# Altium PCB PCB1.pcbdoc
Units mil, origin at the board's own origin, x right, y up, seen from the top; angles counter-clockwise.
Board outline 2086.61 x 986.1 mil, 4 copper layers (Top Layer, AGND, Power, Bottom Layer), stack 62.447 mil thick; 45 components, 23 nets, 118 pads, 113 vias.
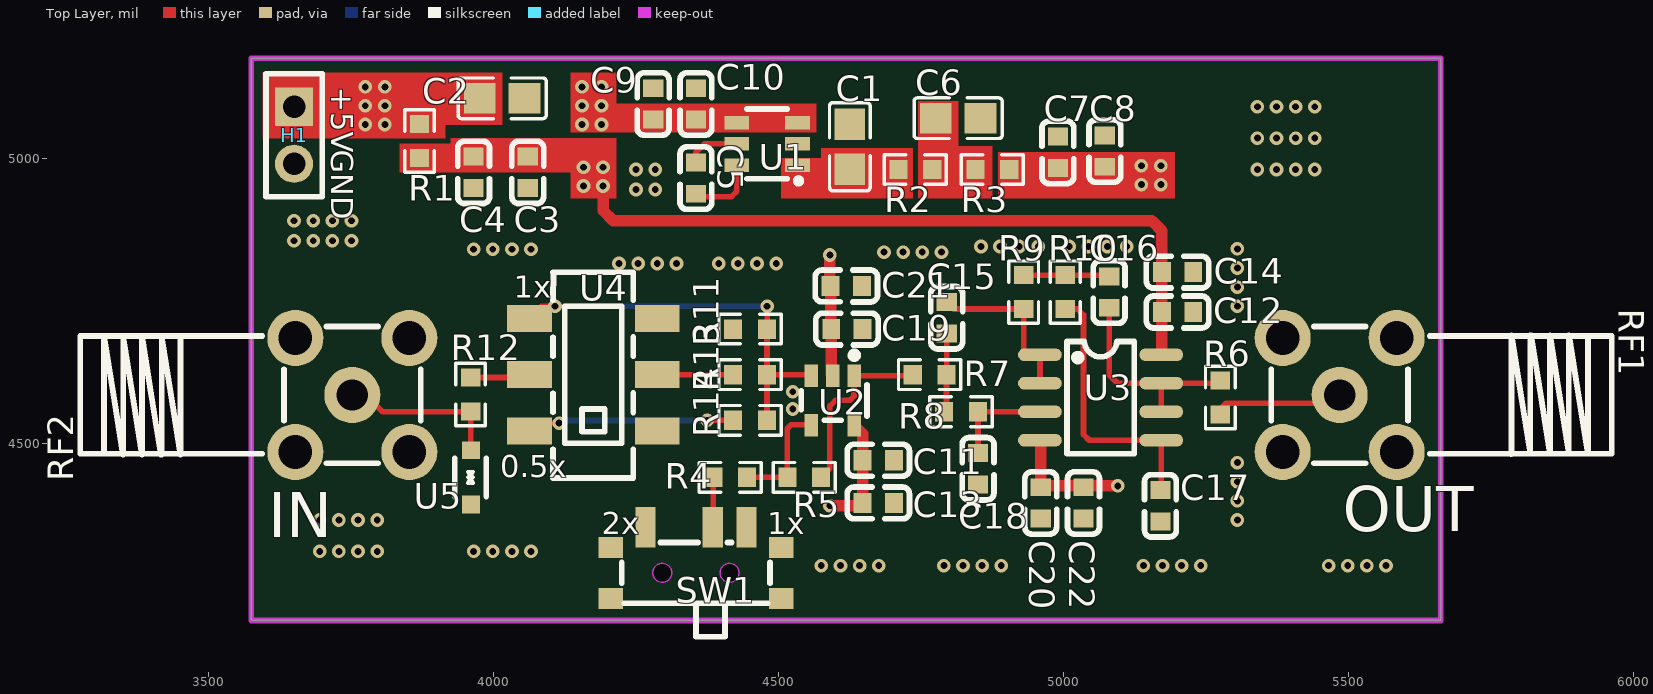
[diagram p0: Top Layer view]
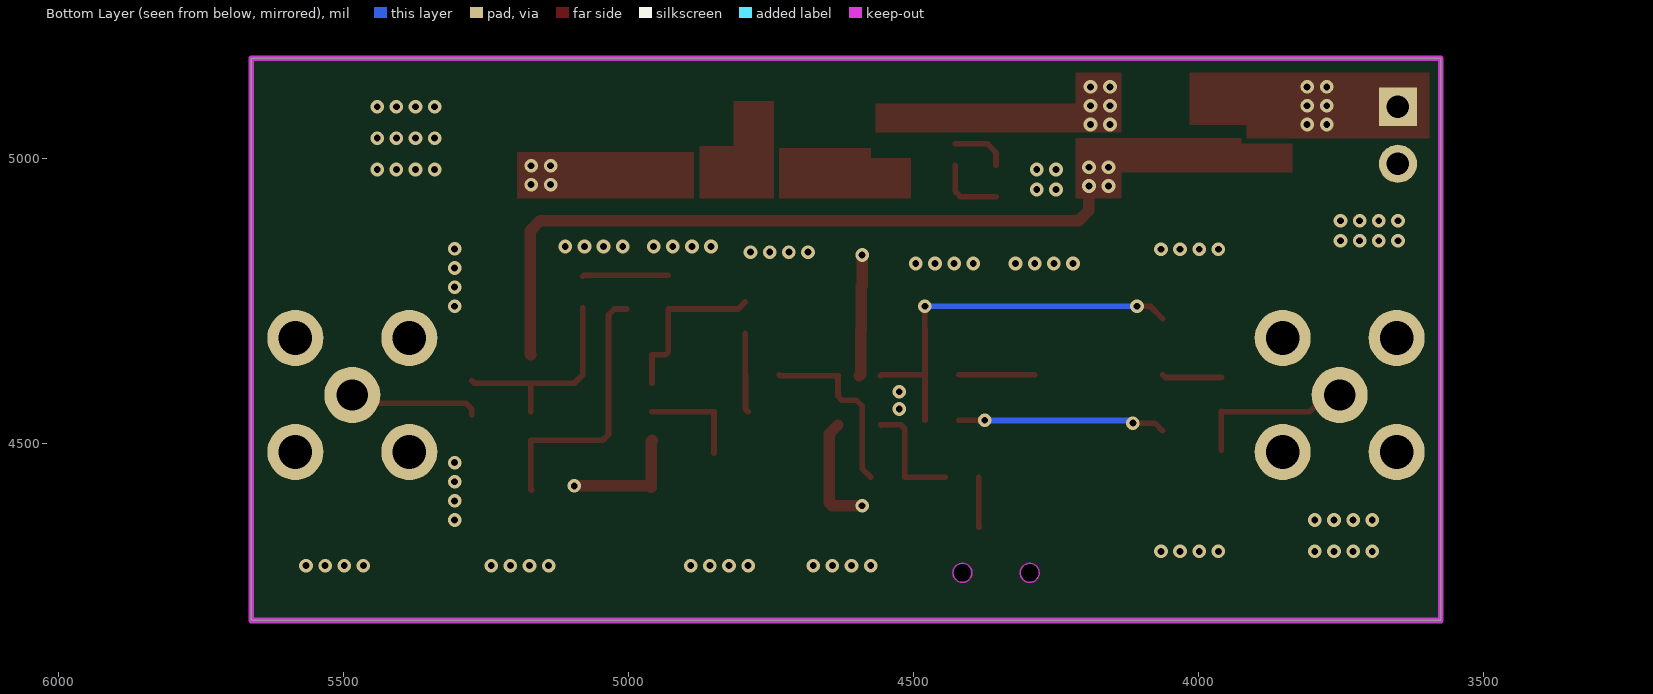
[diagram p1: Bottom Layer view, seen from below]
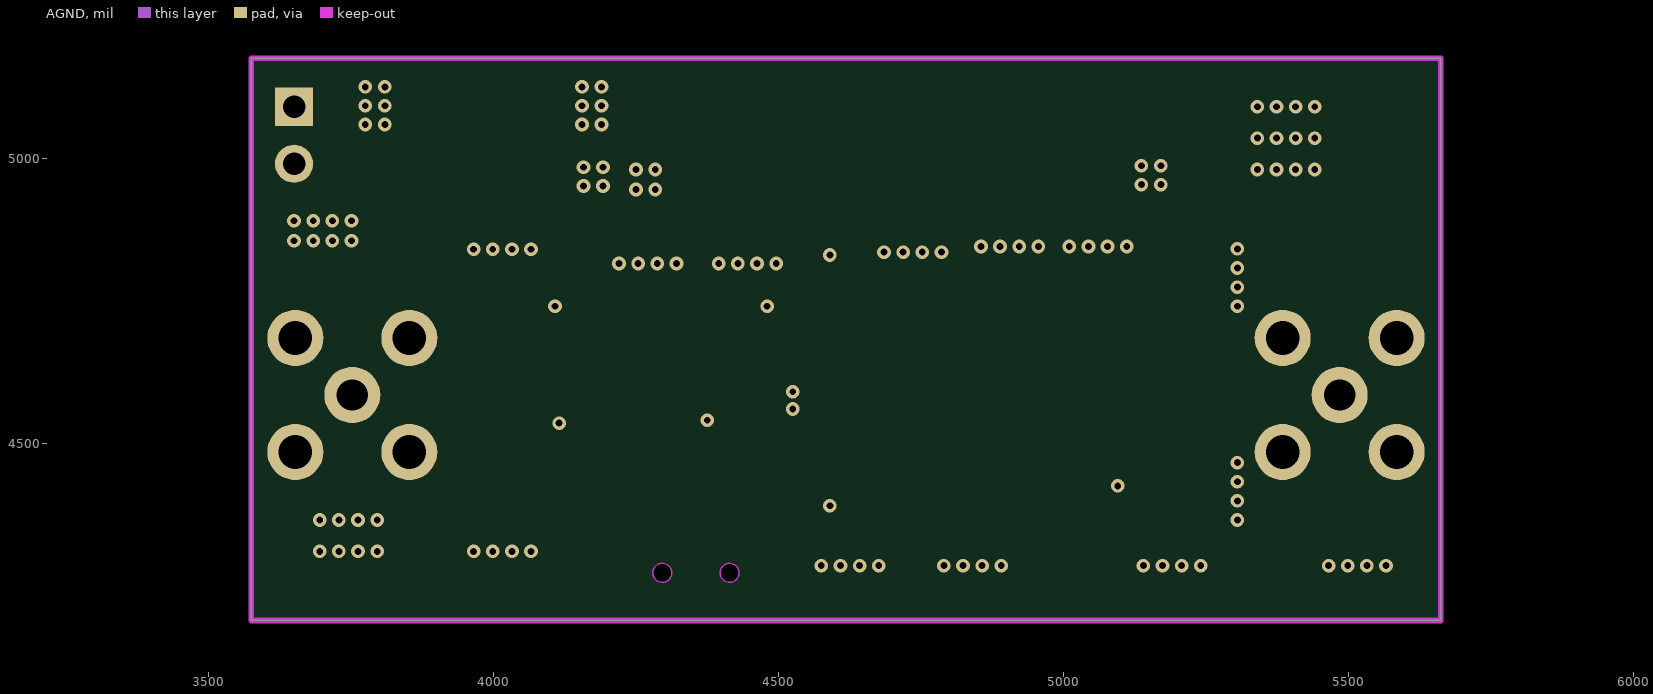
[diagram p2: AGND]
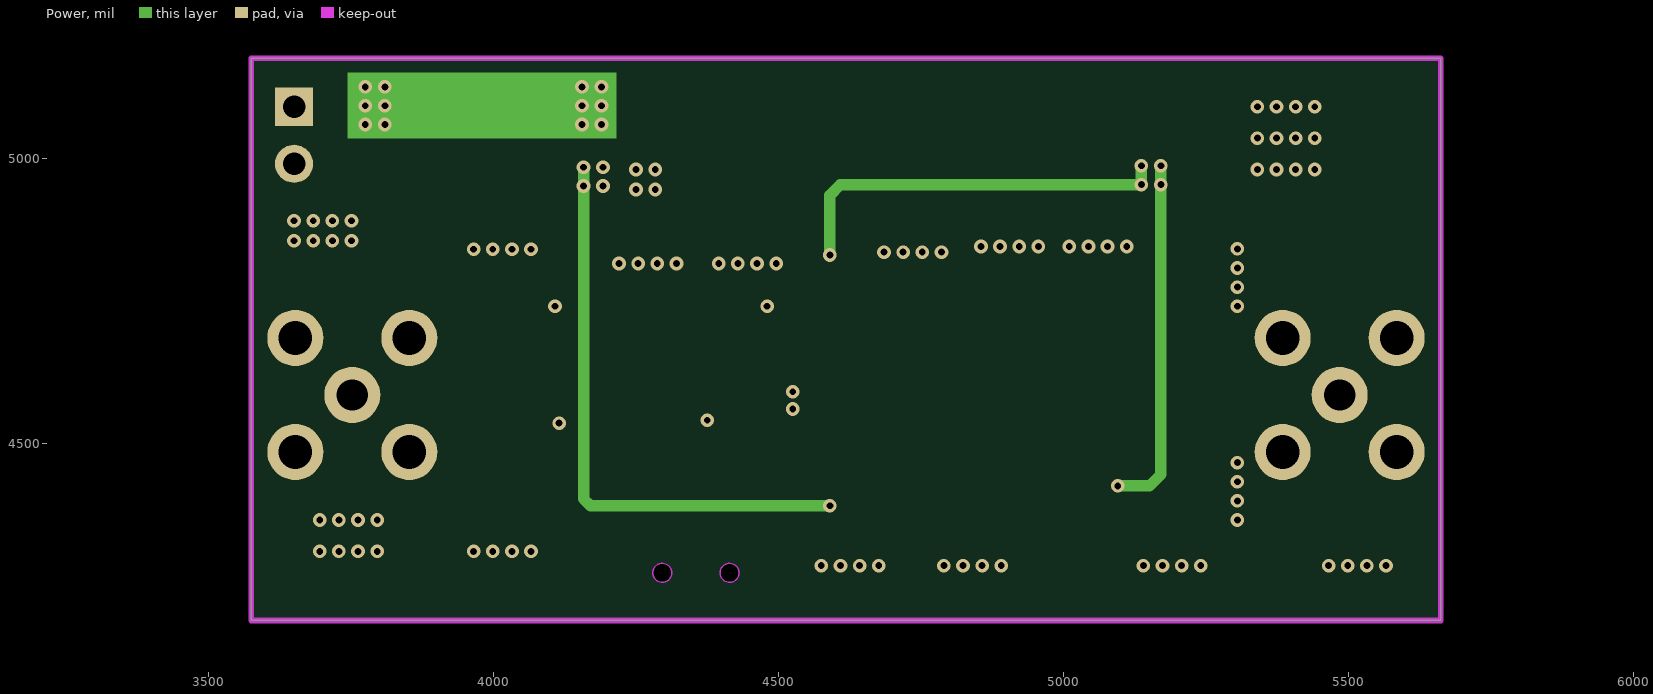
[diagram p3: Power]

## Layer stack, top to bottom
Top Layer: signal copper 1.378
Dielectric1: surface 8.283, 7628 RC49% 8.6mil, Dk 4.4
AGND: signal copper 0.598
Dielectric2: surface 41.929, 1.1mm H/HOZ Copper, Dk 4.43
Power: signal copper 0.598
Dielectric3: surface 8.283, 7628 RC49% 8.6mil, Dk 4.4
Bottom Layer: signal copper 1.378

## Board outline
3575,5175 3575,4188.9 5661.61,4188.9 5661.61,5175

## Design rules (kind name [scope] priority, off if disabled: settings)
BoardOutlineClearance copperThickness2oz_1 [All] p2 off: genericclearance=7.99 ignorepadtopadclearanceinfootprint=FALSE except(0: Arc-SplitContinuation Track-SplitContinuation SMDPad-SplitContinuation THPad-SplitContinuation Via-SplitContinuation Fill-SplitContinuation Region-SplitContinuation Poly-SplitContinuation Text-SplitContinuation Hole-SplitContinuation; 5.98: Arc-CutoutEdge SMDPad-CutoutEdge THPad-CutoutEdge Via-CutoutEdge Fill-CutoutEdge Region-CutoutEdge Text-CutoutEdge; 6.93: Hole-OutlineEdge Hole-CutoutEdge; 10: Poly-OutlineEdge Poly-CutoutEdge; 11.81: Arc-OutlineEdge Track-OutlineEdge SMDPad-OutlineEdge THPad-OutlineEdge Via-OutlineEdge Fill-OutlineEdge Region-OutlineEdge Text-OutlineEdge Track-CutoutEdge)
BoardOutlineClearance copperThickness1oz_1 [All] p4: genericclearance=4.02 ignorepadtopadclearanceinfootprint=FALSE except(0: Arc-SplitContinuation Track-SplitContinuation SMDPad-SplitContinuation THPad-SplitContinuation Via-SplitContinuation Fill-SplitContinuation Region-SplitContinuation Poly-SplitContinuation Text-SplitContinuation Hole-SplitContinuation; 6: SMDPad-CutoutEdge THPad-CutoutEdge Via-CutoutEdge Fill-CutoutEdge Region-CutoutEdge Text-CutoutEdge; 6.93: Hole-OutlineEdge Hole-CutoutEdge; 10: Poly-OutlineEdge Poly-CutoutEdge; 11.8: Arc-OutlineEdge Track-OutlineEdge SMDPad-OutlineEdge THPad-OutlineEdge Via-OutlineEdge Fill-OutlineEdge Region-OutlineEdge Text-OutlineEdge; 11.81: Arc-CutoutEdge Track-CutoutEdge)
Clearance copperThickness2oz [All] p1 off: gap=7.99 ignorepadtopadclearanceinfootprint=FALSE except(5.98: SMDPad-Track SMDPad-SMDPad THPad-Track SMDPad-THPad THPad-THPad Track-Via SMDPad-Via THPad-Via Via-Via Fill-Track Region-Track Fill-SMDPad Region-SMDPad Fill-THPad Region-THPad Fill-Via Region-Via Fill-Fill Fill-Region Region-Region Arc-Track Arc-SMDPad Arc-THPad Arc-Via Fill-Arc Region-Arc Arc-Arc Text-Track SMDPad-Text Text-THPad Text-Via Fill-Text Region-Text Arc-Text Text-Text; 6.93: Hole-Track Hole-SMDPad Hole-THPad Hole-Via Fill-Hole Region-Hole Hole-Arc Hole-Text; 10: Poly-Track Poly-SMDPad Poly-THPad Poly-Via Poly-Fill Poly-Region Poly-Poly Poly-Arc Poly-Text Poly-Hole)
Clearance copperThickness1oz [All] p3: gap=4.02 ignorepadtopadclearanceinfootprint=FALSE except(5.98: SMDPad-Track SMDPad-SMDPad THPad-Track SMDPad-THPad THPad-THPad Track-Via SMDPad-Via THPad-Via Via-Via Fill-Track Region-Track Fill-SMDPad Region-SMDPad Fill-THPad Region-THPad Fill-Via Region-Via Fill-Fill Fill-Region Region-Region; 6: Arc-Track Arc-SMDPad Arc-THPad Arc-Via Fill-Arc Region-Arc Arc-Arc Text-Track SMDPad-Text Text-THPad Text-Via Fill-Text Region-Text Arc-Text Text-Text; 6.93: Hole-Track Hole-SMDPad Hole-THPad Hole-Via Fill-Hole Region-Hole Hole-Arc Hole-Text; 10: Poly-Track Poly-SMDPad Poly-THPad Poly-Via Poly-Fill Poly-Region Poly-Poly Poly-Arc Poly-Text Poly-Hole)
Creepage creepage [All] p1: checkdistance=0 ignoreinternallayers=TRUE applytopolygonpour=TRUE
DiffPairsRouting differentialPair [All] p1: maxlimit=6 minlimit=6 mostfreqgap=6 toplayer_minwidth=5 toplayer_prefwidth=10 toplayer_maxwidth=100 toplayer_mingap=6 toplayer_prefgap=6 toplayer_maxgap=6 midlayer1_minwidth=5 midlayer1_prefwidth=10 midlayer1_maxwidth=100 midlayer1_mingap=6 midlayer1_prefgap=6 midlayer1_maxgap=6 midlayer2_minwidth=5 midlayer2_prefwidth=10 midlayer2_maxwidth=100 midlayer2_mingap=6 midlayer2_prefgap=6 midlayer2_maxgap=6 bottomlayer_minwidth=5 bottomlayer_prefwidth=10 bottomlayer_maxwidth=100 bottomlayer_mingap=6 bottomlayer_prefgap=6 bottomlayer_maxgap=6 maxuncoupledlength=10
HoleToHoleClearance otherClearance [All] p1: gap=11.81 allowstackedmicrovias=TRUE
Length netLength [All] p1: minlimit=0 maxlimit=0
MatchedLengths netLengthTolerance [All] p1: tolerance=1000
PasteMaskExpansion pasteMaskExpansion [All] p1: expansion=0
PlaneConnect innerPlane [All] p1: planeconnectstyle=Relief reliefexpansion=20 reliefentries=4 reliefconductorwidth=10 reliefairgap=10
PolygonConnect "copperRegion_Top Layer" [(InNet('+5V') OR InNet('AGND')) And OnLayer('Top Layer')] p1: connectstyle=Direct reliefconductorwidth=10 reliefentries=4 polygonreliefangle="90 Angle" airgapwidth=10 via.connectstyle=Relief via.reliefconductorwidth=10 via.reliefentries=4 via.polygonreliefangle="90 Angle" via.airgapwidth=10
PolygonConnect "copperRegion_Bottom Layer" [(InNet('+5V') OR InNet('AGND')) And OnLayer('Bottom Layer')] p2: connectstyle=Direct reliefconductorwidth=10 reliefentries=4 polygonreliefangle="90 Angle" airgapwidth=10 via.connectstyle=Relief via.reliefconductorwidth=10 via.reliefentries=4 via.polygonreliefangle="90 Angle" via.airgapwidth=10
PolygonConnect copperRegion_AGND [(InNet('+5V') OR InNet('AGND')) And OnLayer('AGND')] p3: connectstyle=Direct reliefconductorwidth=10 reliefentries=4 polygonreliefangle="90 Angle" airgapwidth=10 smdpad.connectstyle=Relief smdpad.reliefconductorwidth=10 smdpad.reliefentries=4 smdpad.polygonreliefangle="90 Angle" smdpad.airgapwidth=10 via.connectstyle=Relief via.reliefconductorwidth=10 via.reliefentries=4 via.polygonreliefangle="90 Angle" via.airgapwidth=10
PolygonConnect copperRegion_Power [(InNet('+5V') OR InNet('AGND')) And OnLayer('Power')] p4: connectstyle=Direct reliefconductorwidth=10 reliefentries=4 polygonreliefangle="90 Angle" airgapwidth=10 smdpad.connectstyle=Relief smdpad.reliefconductorwidth=10 smdpad.reliefentries=4 smdpad.polygonreliefangle="90 Angle" smdpad.airgapwidth=10 via.connectstyle=Relief via.reliefconductorwidth=10 via.reliefentries=4 via.polygonreliefangle="90 Angle" via.airgapwidth=10
PolygonConnect copperRegion [(InNet('+5V') OR InNet('AGND'))] p5: connectstyle=Direct reliefconductorwidth=10 reliefentries=4 polygonreliefangle="90 Angle" airgapwidth=10 via.connectstyle=Relief via.reliefconductorwidth=10 via.reliefentries=4 via.polygonreliefangle="90 Angle" via.airgapwidth=10
RoutingVias viaSize [All] p1: holewidth=12.01 width=24.02 viastyle="Through Hole" minholewidth=11.81 minwidth=19.68 maxholewidth=248.03 maxwidth=393.7
SolderMaskExpansion solderMaskExpansion [IsVia] p1: expansion=-1000 istentingtop=TRUE
SolderMaskExpansion solderMaskExpansion [All] p2: expansion=2 istentingtop=FALSE
Width copperThickness2oz_2 [All] p1 off: maxlimit=100 minlimit=8 preferedwidth=10
Width copperThickness1oz_2 [All] p2: maxlimit=100 minlimit=5 preferedwidth=10

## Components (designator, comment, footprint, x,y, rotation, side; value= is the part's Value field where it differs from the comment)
C1 "2.2uF" C0805 4625,5020 r90 top
C2 "10uF" C0805 4015,5105 r180 top
C3 "100nF" C0603 4060,4975 r90 top
C4 "1uF" C0603 3965,4975 r90 top
C5 "1uF" C0603 4355,4965 r270 top
C6 "10uF" C0805 4815,5070 r180 top
C7 "100nF" C0603 4990,5010 r270 top
C8 "1uF" C0603 5072.44,5012.44 r270 top
C9 "1uF" C0603 4280,5095 r270 top
C10 "100nF" C0603 4355,5095 r270 top
C11 "100nF" C0603 4675,4470 r180 top
C12 "100nF" C0603 5200,4730 r180 top
C13 "1uF" C0603 4675,4395 r180 top
C14 "1uF" C0603 5200,4800 r180 top
C15 "150pF" C0603 4795,4720 r270 top
C16 "27pF" C0603 5080,4765 r270 top
C17 "22pF" C0603 5170,4390 r90 top
C18 "22pF" C0603 4850,4455 r90 top
C19 "100nF" C0603 4620,4700 r0 top
C20 "100nF" C0603 4960,4395 r270 top
C21 "1uF" C0603 4618.94,4775.69 r0 top
C22 "1uF" C0603 5035,4395 r270 top
H1 "" HDR-TH_2P-P2.54-V-F 3650,5040 r270 top
R1 "10Ω" R0603 3870,5030 r270 top
R2 "1Ω" R0603 4740,4980 r0 top
R3 "10Ω" R0603 4875,4980 r0 top
R4 "499Ω" R0603 4415,4440 r0 top
R5 "499Ω" R0603 4545,4440 r0 top
R6 "22Ω" R0603 5275,4580 r270 top
R7 "180Ω" R0603 4765,4620 r0 top
R8 "180Ω" R0603 4820,4555 r0 top
R9 "430Ω" R0603 4930,4765 r90 top
R10 "430Ω" R0603 5003.03,4765 r270 top
R11 "10kΩ" R0603 4450,4700 r0 top
R12 "100Ω" R0603 3959.66,4585.34 r90 top
R13 "1kΩ" R0603 4450,4620 r0 top
R14 "820Ω" R0603 4450,4540 r0 top
RF1 "6GHz" SMA-TH_SMA-KWE902 5484.45,4584.45 r270 top
RF2 "6GHz" SMA-TH_SMA-KWE902 3752.17,4584.45 r90 top
SW1 "MK-12C02-G025" SW-SMD_MK-12C02-G025 4355,4290 r0 top
U1 "LM2776DBVR" SOT-23-6_L2.9-W1.6-P0.95-LS2.8-BR 4480,5025 r0 top
U2 "OPA830IDBVR" SOT-23-5_L2.9-W1.6-P0.95-LS2.8-BR 4595,4575 r90 top
U3 "OPA2830IDR" SOIC-8_L5.0-W4.0-P1.27-LS6.0-BL 5065,4580 r270 top
U4 "HX MST22D18G2" SW-SMD_MST22D18G2 4175,4620 r90 top
U5 "WPE12VD3ULA" SOD-323_L1.7-W1.3-LS2.5-BI 3960,4440 r90 top

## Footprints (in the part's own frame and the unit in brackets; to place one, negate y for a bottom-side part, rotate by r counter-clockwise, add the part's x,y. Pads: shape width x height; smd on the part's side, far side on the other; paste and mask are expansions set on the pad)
C0603 [mm]
  rect 0.8x0.9 smd: 1(-0.7,0) 2(0.7,0)
  silkscreen extent -1.39,-0.71 1.39,0.71
C0805 [mm]
  rect 1.41x1.35 smd paste-100 mask+0.051: 1(-1,0) 2(1,0)
  silkscreen extent -1.96,-0.9 1.96,0.9
HDR-TH_2P-P2.54-V-F [mm]
  rect 1.7x1.7 hole 1: 1(-1.27,0)
  round 1.7 hole 1: 2(1.27,0)
  silkscreen extent -2.74,-1.25 2.74,1.25
R0603 [mil]
  rect 31.75x34.02 smd paste-3937.01 mask+2: 1(-29.66,0) 2(29.66,0)
  silkscreen extent -55,-26 55,26
SMA-TH_SMA-KWE902 [mm]
  round 2.5 hole 1.5: 1(-2.54,2.54) 2(2.54,2.54) 3(2.54,-2.54) 4(-2.54,-2.54)
  round 2.5 hole 1.4: 5(0,0)
  silkscreen extent -3.05,-3.05 3.05,12.12
SOD-323_L1.7-W1.3-LS2.5-BI [mm]
  rect 0.8x0.8 smd: 1(-1.205,0) 2(1.205,0)
  silkscreen extent -0.86,-0.68 0.84,0.72
SOIC-8_L5.0-W4.0-P1.27-LS6.0-BL [mil]
  oval 22.38x76.78 smd: 1(-75,-106.5) 2(-25,-106.5) 3(25,-106.5) 4(75,-106.5) 5(75,106.5) 6(25,106.5) 7(-25,106.5) 8(-75,106.5)
  silkscreen extent -98,-59 98,59
SOT-23-5_L2.9-W1.6-P0.95-LS2.8-BR [mm]
  rect 1x0.6 smd paste+0 mask+0.05: 1(1.1,-0.95) 2(1.1,0) 3(1.1,0.95) 4(-1.1,0.95) 5(-1.1,-0.95)
  silkscreen extent -0.89,-1.52 2.16,1.4
SOT-23-6_L2.9-W1.6-P0.95-LS2.8-BR [mm]
  rect 1.1x0.6 smd paste+0 mask+0.051: 1(1.35,-0.95) 2(1.35,0) 3(1.35,0.95) 4(-1.35,0.95) 5(-1.35,0) 6(-1.35,-0.95)
  silkscreen extent -0.9,-1.78 1.52,1.55
SW-SMD_MK-12C02-G025 [mm]
  rect 0.9x1.8 smd: 1(-2.25,1.583) 2(0.75,1.583) 3(2.25,1.583)
  rect 1.1x0.93 smd: 4(3.8,0.687) 5(3.8,-1.583) 6(-3.8,-1.583) 7(-3.8,0.687)
  Board Outline Layer circle w0.003: c1.5,-0.448 r0.425
  Board Outline Layer circle w0.003: c-1.5,-0.448 r0.425
  Board Outline Layer region: 1.925,-0.448 1.883,-0.633 1.765,-0.781 1.595,-0.863 1.405,-0.863 1.235,-0.781 1.117,-0.633 1.075,-0.448 1.075,-0.448 1.117,-0.264 1.235,-0.116 1.405,-0.034 1.595,-0.034 1.765,-0.116 1.883,-0.264 1.925,-0.448
  Board Outline Layer region: 1.925,-0.448 1.916,-0.537 1.888,-0.621 1.844,-0.698 1.784,-0.764 1.712,-0.816 1.631,-0.853 1.544,-0.871 1.456,-0.871 1.369,-0.853 1.288,-0.816 1.216,-0.764 1.156,-0.698 1.112,-0.621 1.084,-0.537 1.075,-0.448 1.084,-0.36 1.112,-0.275 1.156,-0.199 1.216,-0.132 1.288,-0.08 1.369,-0.044 1.456,-0.026 1.544,-0.026 1.631,-0.044 1.712,-0.08 1.784,-0.132 1.844,-0.199 1.888,-0.275 1.916,-0.36
  Board Outline Layer region: -1.075,-0.448 -1.117,-0.633 -1.235,-0.781 -1.405,-0.863 -1.595,-0.863 -1.765,-0.781 -1.883,-0.633 -1.925,-0.448 -1.925,-0.448 -1.883,-0.264 -1.765,-0.116 -1.595,-0.034 -1.405,-0.034 -1.235,-0.116 -1.117,-0.264 -1.075,-0.448
  Board Outline Layer region: -1.075,-0.448 -1.084,-0.537 -1.112,-0.621 -1.156,-0.698 -1.216,-0.764 -1.288,-0.816 -1.369,-0.853 -1.456,-0.871 -1.544,-0.871 -1.631,-0.853 -1.712,-0.816 -1.784,-0.764 -1.844,-0.698 -1.888,-0.621 -1.916,-0.537 -1.925,-0.448 -1.916,-0.36 -1.888,-0.275 -1.844,-0.199 -1.784,-0.132 -1.712,-0.08 -1.631,-0.044 -1.544,-0.026 -1.456,-0.026 -1.369,-0.044 -1.288,-0.08 -1.216,-0.132 -1.156,-0.199 -1.112,-0.275 -1.084,-0.36
  Multi-Layer board cut-out: 1.925,-0.448 1.883,-0.633 1.765,-0.781 1.595,-0.863 1.405,-0.863 1.235,-0.781 1.117,-0.633 1.075,-0.448 1.075,-0.448 1.117,-0.264 1.235,-0.116 1.405,-0.034 1.595,-0.034 1.765,-0.116 1.883,-0.264 1.925,-0.448
  Multi-Layer board cut-out: -1.075,-0.448 -1.117,-0.633 -1.235,-0.781 -1.405,-0.863 -1.595,-0.863 -1.765,-0.781 -1.883,-0.633 -1.925,-0.448 -1.925,-0.448 -1.883,-0.264 -1.765,-0.116 -1.595,-0.034 -1.405,-0.034 -1.235,-0.116 -1.117,-0.264 -1.075,-0.448
  silkscreen extent -3.3,-3.3 3.3,0.9
SW-SMD_MST22D18G2 [mm]
  rect 1.2x2 smd: 1(-2.5,2.85) 2(0,2.85) 3(2.5,2.85) 4(-2.5,-2.85) 5(0,-2.85) 6(2.5,-2.85)
  silkscreen extent -4.6,-1.78 4.57,1.8

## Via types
v1: diameter 24.02, hole 12, Top Layer to Bottom Layer, 113 vias

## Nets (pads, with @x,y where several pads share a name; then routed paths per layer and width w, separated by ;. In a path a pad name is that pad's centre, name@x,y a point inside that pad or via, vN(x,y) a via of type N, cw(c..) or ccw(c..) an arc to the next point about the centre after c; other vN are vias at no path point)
$1N4: R12.1 RF2.5 U5.2 | length 285.7
  Top Layer w10: RF2.5@3755,4585 3775,4585 3805,4555 3958.98,4555 R12.1 3960,4555.34 U5.2
$1N5: R11.2 R13.2 R14.2 U2.3 U4.3 | length 704.9
  Top Layer w10: U4.3 4084.38,4740 v1(4107.8,4740) ; R14.2 R13.2 ; v1(4480,4740) 4480,4700.34 R11.2 R13.2 ; U2.3 4555.91,4620 R13.2
  Bottom Layer w10: v1(4107.8,4740) v1(4480,4740)
$1N9: R6.2 RF1.5 | length 228.8
  Top Layer w10: R6.2 5275,4560 5285,4570 5468.44,4570 RF1.5@5483.67,4585.23
$1N23: R5.2 R7.1 U2.1 | length 320.5
  Top Layer w10: R5.2 4590,4455.34 4590,4565 4600,4575 4625,4575 4632.4,4582.4 U2.1 4733.65,4618.31 R7.1
$1N24: R4.2 R5.1 U2.4 | length 201.2
  Top Layer w10: R4.2 R5.1 4515.34,4525.34 4522.07,4532.07 4557.21,4532.07 U2.4
$1N25: R4.1 SW1.2 | length 88
  Top Layer w10: SW1.2 4385.34,4353.15 R4.1
$1N28: C15.2 R7.2 R8.1 | length 139.4
  Top Layer w10: R8.1 4794.66,4559.32 R7.2 4795,4620.34 C15.2
$1N29: C18.2 R8.2 U3.3 | length 181.4
  Top Layer w10: C18.2 4850,4554.66 R8.2 U3.3
$1N30: C15.1 R9.1 U3.1 U3.2 | length 296
  Top Layer w10: C15.1 4807.22,4735.34 R9.1 4930,4660 4935,4655 U3.1 U3.2
$1N32: C16.1 R9.2 R10.1 | length 150.9
  Top Layer w10: R9.2 R10.1 5077.9,4794.66 C16.1
$1N33: C17.2 R10.2 U3.5 | length 475
  Top Layer w10: R10.2 5024.66,4735.34 5035,4725 5035,4515 5045,4505 U3.5 5171.5,4419.06 C17.2
$1N36: C16.2 R6.1 U3.6 U3.7 | length 370.6
  Top Layer w10: C16.2 5080,4620 5095,4605 U3.7 ; U3.6 U3.7 ; R6.1 5270.34,4605 U3.7
$1N46: R12.2 U4.2 | length 105.2
  Top Layer w10: R12.2 4057.8,4615 U4.2
$1N51: R14.1 U4.1 | length 365.2
  Top Layer w10: U4.1 4076.22,4535 v1(4115,4535) ; v1(4375,4540) R14.1
  Bottom Layer w10: v1(4115,4535) 4119.73,4539.73 4374.73,4539.73 v1(4375,4540)
$1N53: R13.1 U4.5 | length 133.1
  Top Layer w10: U4.5 R13.1
$1N58: C5.1 U1.5 | length 100.5
  Top Layer w10: C5.1@4355,4987.56 4355,5010 4370,5025 U1.5
$1N59: C5.2 U1.6 | length 121.5
  Top Layer w10: C5.2@4355,4932.44 4417.44,4932.44 4426.85,4941.85 U1.6
$1N62: C6.2 R2.2 R3.1
+5V: C2.2 C9.2 C10.2 H1.1 R1.1 U1.3 U1.4
  other v1: 3775,5058.94 3809.23,5058.94 4155,5058.94 4189.23,5058.94 3775,5091.97 3809.23,5091.97 4155,5091.97 4189.23,5091.97 3775,5125 3809.23,5125 4155,5125 4189.23,5125
-5V: C1.1 R2.1 U1.1
AGND: C1.2 C2.1 C3.1 C4.1 C6.1 C7.1 C8.1 C9.1 C10.1 C11.1 C12.1 C13.1 C14.1 C17.1 C18.1 C19.2 C20.2 C21.2 C22.2 H1.2 R11.1 RF1.1 RF1.2 RF1.3 RF1.4 RF2.1 RF2.2 RF2.3 RF2.4 SW1.1 SW1.4 SW1.5 SW1.6 SW1.7 U1.2 U4.4 U5.1
  other v1: 4575,4285 4608.6,4285 4642.2,4285 4675.8,4285 4790,4285 4823.6,4285 4857.2,4285 4890.8,4285 5140,4285 5173.6,4285 5207.2,4285 5240.8,4285 5465,4285 5498.6,4285 5532.2,4285 5565.8,4285 3695,4310 3728.6,4310 3762.2,4310 3795.8,4310 3965,4310 3998.6,4310 4032.2,4310 4065.8,4310 3695,4365 3728.6,4365 3762.2,4365 3795.8,4365 5305,4365 5305,4398.6 5305,4432.2 5305,4465.8 4525,4560 4525,4590 5305,4740 5305,4773.6 5305,4807.2 4220,4815 4253.6,4815 4287.2,4815 4320.8,4815 4395,4815 4428.6,4815 4462.2,4815 4495.8,4815 4685,4835 4718.6,4835 4752.2,4835 4785.8,4835 3965,4840 3998.6,4840 4032.2,4840 4065.8,4840 5305,4840.8 4855,4845 4888.6,4845 4922.2,4845 4955.8,4845 5010,4845 5043.6,4845 5077.2,4845 5110.8,4845 3650,4855 3683.6,4855 3717.2,4855 3750.8,4855 3650,4890 3683.6,4890 3717.2,4890 3750.8,4890 4250,4945 4283.6,4945 4250,4980 4283.6,4980 5340,4980 5373.6,4980 5407.2,4980 5440.8,4980 5340,5035 5373.6,5035 5407.2,5035 5440.8,5035 5340,5090 5373.6,5090 5407.2,5090 5440.8,5090
V+: C3.2 C4.2 C11.2 C12.2 C13.2 C14.2 R1.2 U2.5 U3.8 | length 2510.5
  Top Layer w20: v1(4192.12,4984.02) v1(4192.12,4950.98) 4192.12,4907.88 4210,4890 5155,4890 5172.44,4872.56 C14.2 C12.2 5172.44,4655.94 U3.8 ; v1(4590,4390) 4642.44,4390 C13.2 C11.2 4647.44,4516.65 U2.5
  Power w20: v1(4157.88,4984.02) v1(4157.88,4950.98) 4157.88,4402.12 4170,4390 v1(4590,4390)
V-: C7.2 C8.2 C19.1 C20.1 C21.1 C22.1 R3.2 U2.2 U3.4 | length 1750.6
  Top Layer w20: v1(4590,4830) 4590,4777.06 C21.1 4591.38,4701.06 C19.1 4592.44,4620.87 U2.2 ; U3.4 4960,4503.5 C20.1 4962.44,4425 v1(5095,4425)
  Power w20: v1(4590,4830) 4590,4935 4608.48,4953.48 v1(5136.5,4953.48) v1(5136.5,4986.52) ; v1(5095,4425) 5150.73,4425 5170.73,4445 v1(5170.73,4953.48) v1(5170.73,4986.52)
pads on no net: SW1.3 U4.6

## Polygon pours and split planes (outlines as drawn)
AGND on Top Layer (solid, remove dead copper, pour order 0): 3500,5235 3500,4040 5745,4040 5745,5235
AGND on AGND (solid, remove dead copper): 3510,5220 3510,4050 5800,4050 5800,5220
AGND on Power (solid, remove dead copper): 3475,5265 3475,4100 5770,4100 5770,5265
AGND on Bottom Layer (solid, remove dead copper, pour order 2): 3470,5275 3470,4120 5735,4120 5735,5275

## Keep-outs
Board Outline Layer:
  the board outline again, w10

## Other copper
Top Layer:
  region net +5V: 3595,5150 4015,5150 4015,5058.4 3915,5058.4 3915,5034.99 3595,5034.99
  region net V+: 3835,5025 3925.28,5025 3925.28,5035 4215,5035 4215,4975 3835.02,4975 3835,4975.02
  region net +5V: 4135,5095 4565.88,5095 4565.88,5045 4135,5045
  region net +5V: 4135,5150 4135,5081.41 4215,5081.41 4215,5150
  region net -5V: 4505,5000 4575,5000 4575,5017.65 4735,5017.65 4735,4930 4505,4930
  region net $1N62: 4745,5099.57 4815,5099.57 4815,5020.38 4874.62,5020.38 4875,5020 4875,4930 4745,4930
  region net V-: 4885,5010 4885,4930 5195,4930 5195,5010
  region net V+: 4135,5005 4135,4930 4215,4930 4215,5005
Power:
  region net +5V: 3744.59,5150 3744.59,5035 4215,5035 4215,5150

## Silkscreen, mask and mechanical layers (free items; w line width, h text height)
Top Silkscreen Layer:
  text "+5V" at 3715,5125 h39.37 r270
  text "GND" at 3715,5015 h39.37 r270
  text "1x" at 4035,4755 h39.37
  text "0.5x" at 4011.85,4440 h39.37
  text "OUT" at 5490,4345 h78.74
  text "2x" at 4190,4340 h39.37
  text "1x" at 4480,4340 h39.37
  text "IN" at 3605,4335 h78.74

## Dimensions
6315,5200 to 6315,4176.38 on Document Layer
3955,5065 to 5310,5065 on Document Layer
5330.59,5576.02 to 3913.27,5581.03 on Document Layer
4265,3630 to 4973.66,3630 on Document Layer
4540,3365 to 5662.13,3365 on Document Layer
4165,3355 to 3574.45,3355 on Document Layer
4124.99,3000 to 3577.21,3000 on Document Layer
4224.99,3000 to 5664.3,3000 on Document Layer
3000,4800 to 3000,5175 on Document Layer
3045,4438.9 to 3045,4188.9 on Document Layer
